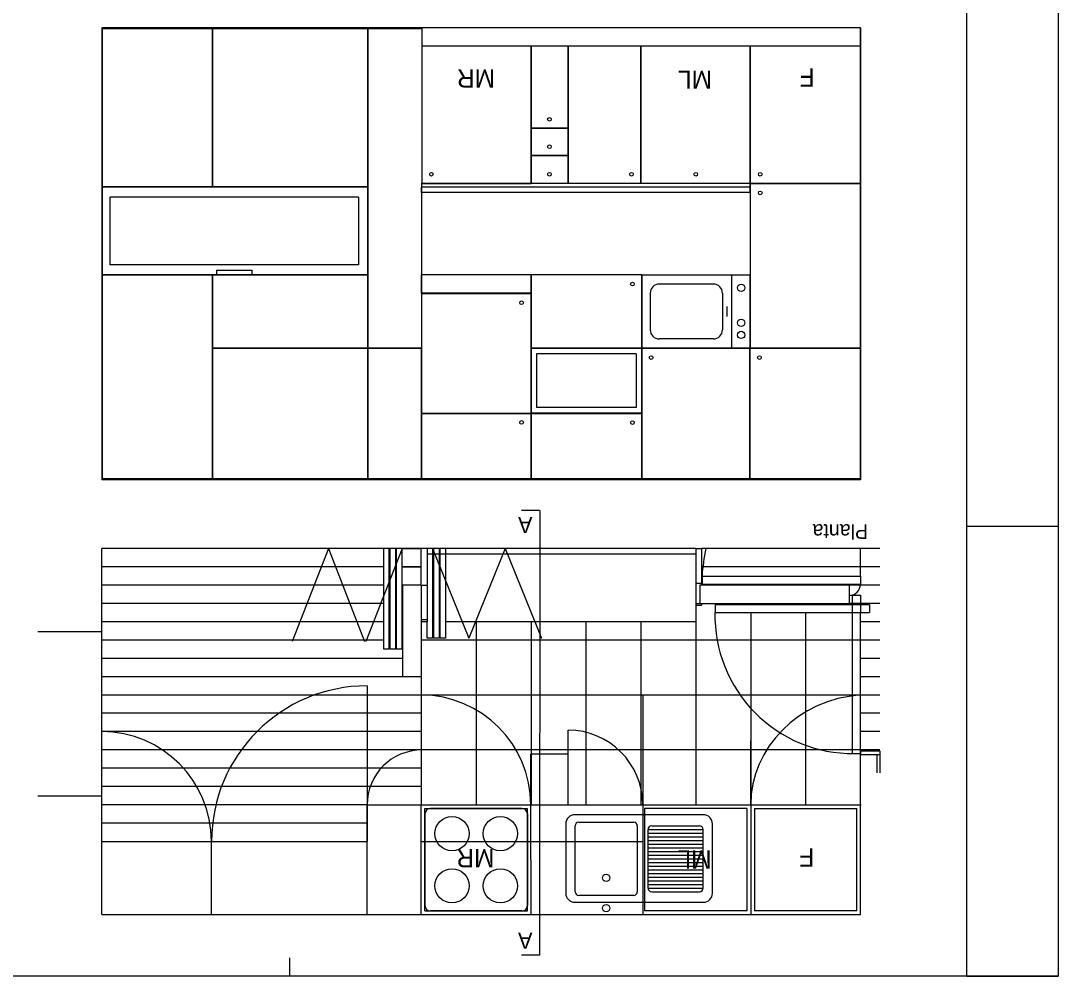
# Model space of a CAD drawing. Extents: x 1306.3 to 1323.2, y -308.3 to -299.9.
# Drawn here: x 1317.51 to 1323.18, y -308.35 to -303.12 of the extents above; entities that cross this region are included whole.
import ezdxf

# ---------------------------------------------------------------- set-up
doc = ezdxf.new("R2010")
doc.units = 0
for name, color, linetype in [('Level 1', 7, 'Continuous'), ('Level 10', 7, 'Continuous'), ('Level 11', 7, 'Continuous'), ('Level 13', 7, 'Continuous'), ('Level 2', 7, 'Continuous'), ('Level 3', 7, 'Continuous'), ('Level 31', 7, 'Continuous'), ('Level 37', 7, 'Continuous'), ('Level 4', 7, 'Continuous'), ('Level 59', 7, 'Continuous'), ('Level 60', 7, 'Continuous'), ('Level 62', 7, 'Continuous')]:
    doc.layers.add(name, color=color, linetype=linetype)

msp = doc.modelspace()

# ---------------------------------------------------------------- linework, layer by layer
at = {"layer": 'Level 1'}
for p, q in [((1322.0966, -303.1632), (1317.9505, -303.1632)), ((1317.9505, -303.1632), (1317.9505, -305.6332)), ((1322.0966, -303.1632), (1322.0966, -305.6332)), ((1322.0966, -305.6332), (1317.9505, -305.6332)), ((1317.9505, -306.4612), (1317.9505, -306.0087)), ((1319.6966, -306.2087), (1319.6966, -306.0087)), ((1319.7286, -306.0087), (1319.698, -306.0087)), ((1319.7286, -306.0087), (1319.7286, -306.4087)), ((1321.1966, -306.0087), (1321.1966, -306.3187)), ((1321.1966, -306.0087), (1321.2286, -306.0087)), ((1321.2286, -306.0087), (1321.2286, -306.2087)), ((1321.2286, -306.1987), (1321.1966, -306.1987)), ((1319.5966, -306.7087), (1319.5966, -306.2087)), ((1319.6966, -306.2087), (1319.5966, -306.2087)), ((1319.6966, -306.2087), (1319.6966, -306.7087)), ((1319.6966, -306.2087), (1319.7286, -306.2087)), ((1321.1966, -306.2087), (1321.1966, -306.3087)), ((1322.0366, -306.2087), (1321.2186, -306.2087)), ((1321.2186, -306.2087), (1321.2186, -306.3087)), ((1322.0366, -306.3087), (1322.0366, -306.2087)), ((1322.0366, -306.3087), (1322.0366, -306.2087)), ((1321.1966, -306.3087), (1322.0366, -306.3087)), ((1321.1966, -306.3087), (1322.0366, -306.3087)), ((1321.2186, -306.3087), (1322.0366, -306.3087)), ((1321.2286, -306.3087), (1321.2286, -306.3187)), ((1321.1966, -306.3187), (1321.2286, -306.3187)), ((1319.7286, -306.3987), (1319.6966, -306.3987)), ((1319.7286, -306.4087), (1319.6966, -306.4087)), ((1317.6005, -306.4612), (1317.9505, -306.4612)), ((1319.6966, -306.7087), (1319.5966, -306.7087)), ((1322.0966, -307.1337), (1322.2016, -307.1337)), ((1322.0966, -308.0087), (1322.0966, -307.1337)), ((1322.0966, -308.0087), (1322.0966, -307.1337)), ((1322.1866, -307.1337), (1322.1866, -307.2337)), ((1322.2016, -307.1337), (1322.2016, -307.2337)), ((1317.9505, -307.3612), (1317.6005, -307.3612)), ((1317.9505, -308.0087), (1317.9505, -307.3587)), ((1317.9505, -308.0087), (1317.9505, -307.3612)), ((1317.9505, -308.0087), (1322.0966, -308.0087)), ((1319.3966, -308.0087), (1322.0966, -308.0087))]:
    msp.add_line(p, q, dxfattribs=at)
at = {"layer": 'Level 10'}
for p, q in [((1319.6966, -306.0087), (1317.9505, -306.0087)), ((1319.5916, -306.0087), (1319.698, -306.0087)), ((1322.2016, -306.0087), (1321.2286, -306.0087)), ((1319.4916, -306.1087), (1317.9505, -306.1087)), ((1319.5916, -306.1087), (1319.698, -306.1087)), ((1319.6966, -306.1087), (1319.5916, -306.1087)), ((1322.2016, -306.1087), (1321.2286, -306.1087)), ((1319.4916, -306.2087), (1317.9505, -306.2087)), ((1319.5966, -306.2087), (1319.5916, -306.2087)), ((1322.2016, -306.2087), (1322.0366, -306.2087)), ((1319.4916, -306.3087), (1317.9505, -306.3087)), ((1319.5966, -306.3087), (1319.5916, -306.3087)), ((1322.2016, -306.3087), (1322.0366, -306.3087)), ((1321.1966, -306.3587), (1321.1966, -307.4087)), ((1321.4966, -306.3587), (1321.4966, -307.4087)), ((1321.7966, -306.3587), (1321.7966, -307.4087)), ((1322.0966, -307.1137), (1322.0966, -306.3587)), ((1319.4916, -306.4087), (1317.9505, -306.4087)), ((1319.5966, -306.4087), (1319.5916, -306.4087)), ((1319.9966, -306.4087), (1319.9966, -307.4087)), ((1320.2966, -306.4087), (1320.2966, -307.4087)), ((1320.5966, -306.4087), (1320.5966, -307.4087)), ((1320.8966, -306.4087), (1320.8966, -307.4087)), ((1322.2016, -306.4087), (1322.0966, -306.4087)), ((1319.4916, -306.5087), (1317.9505, -306.5087)), ((1319.5966, -306.5087), (1319.5916, -306.5087)), ((1322.0966, -306.5087), (1319.6966, -306.5087)), ((1322.2016, -306.5087), (1322.0966, -306.5087)), ((1319.5966, -306.6087), (1317.9505, -306.6087)), ((1322.2016, -306.6087), (1322.0966, -306.6087)), ((1319.5966, -306.7087), (1317.9505, -306.7087)), ((1319.6966, -306.7087), (1319.6966, -307.4057)), ((1322.2016, -306.7087), (1322.0966, -306.7087)), ((1322.0966, -306.8087), (1317.9505, -306.8087)), ((1322.2016, -306.8087), (1322.0966, -306.8087)), ((1319.6966, -306.9087), (1317.9505, -306.9087)), ((1322.2016, -306.9087), (1322.0966, -306.9087)), ((1319.6966, -307.0087), (1317.9505, -307.0087)), ((1322.2016, -307.0087), (1322.0966, -307.0087)), ((1322.0966, -307.1087), (1317.9505, -307.1087)), ((1322.2016, -307.1087), (1322.0966, -307.1087)), ((1319.6966, -307.2087), (1317.9505, -307.2087)), ((1319.6966, -307.3087), (1317.9505, -307.3087)), ((1319.4005, -307.4087), (1317.9505, -307.4087)), ((1319.4005, -307.5087), (1317.9505, -307.5087))]:
    msp.add_line(p, q, dxfattribs=at)
at = {"layer": 'Level 11'}
for p, q in [((1320.2946, -304.5132), (1319.6986, -304.5132)), ((1319.6986, -304.6132), (1319.6986, -304.5132)), ((1320.2946, -304.5132), (1320.2946, -304.6132)), ((1320.9026, -304.5132), (1320.9026, -304.9132)), ((1320.9026, -304.5132), (1321.4926, -304.5132)), ((1321.3926, -304.5132), (1321.3926, -304.9132)), ((1321.4926, -304.5132), (1321.4926, -304.9132)), ((1321.2926, -304.5632), (1320.9976, -304.5632)), ((1320.2946, -304.6132), (1319.6986, -304.6132)), ((1320.9476, -304.6132), (1320.9476, -304.8132)), ((1321.3426, -304.6132), (1321.3426, -304.8132)), ((1321.3671, -304.6864), (1321.3671, -304.7399)), ((1321.2926, -304.8632), (1320.9976, -304.8632)), ((1321.4926, -304.9132), (1320.9026, -304.9132)), ((1320.2466, -307.4286), (1319.7466, -307.4286)), ((1321.5166, -307.4287), (1322.0766, -307.4287)), ((1321.5166, -307.4287), (1321.5166, -307.9887)), ((1322.0766, -307.9887), (1322.0766, -307.4287)), ((1319.7166, -307.4586), (1319.7166, -307.9586)), ((1320.2766, -307.4586), (1320.2766, -307.9586)), ((1320.557, -307.5036), (1320.857, -307.5036)), ((1320.537, -307.8836), (1320.537, -307.5236)), ((1320.877, -307.5236), (1320.877, -307.8836)), ((1320.9355, -307.8636), (1320.9355, -307.5436)), ((1320.9355, -307.5436), (1321.237, -307.5436)), ((1320.9555, -307.5236), (1321.217, -307.5236)), ((1321.237, -307.8636), (1321.237, -307.5436)), ((1320.9355, -307.5636), (1321.237, -307.5636)), ((1320.9355, -307.5836), (1321.237, -307.5836)), ((1320.9355, -307.6036), (1321.237, -307.6036)), ((1320.9355, -307.6236), (1321.237, -307.6236)), ((1320.9355, -307.6436), (1321.237, -307.6436)), ((1320.9355, -307.6636), (1321.237, -307.6636)), ((1320.9355, -307.6836), (1321.237, -307.6836)), ((1320.9355, -307.7036), (1321.237, -307.7036)), ((1320.9355, -307.7236), (1321.237, -307.7236)), ((1320.9355, -307.7436), (1321.237, -307.7436)), ((1320.9355, -307.7636), (1321.237, -307.7636)), ((1320.9355, -307.7836), (1321.237, -307.7836)), ((1320.9355, -307.8036), (1321.237, -307.8036)), ((1320.9355, -307.8236), (1321.237, -307.8236)), ((1320.9355, -307.8436), (1321.237, -307.8436)), ((1320.9355, -307.8636), (1321.237, -307.8636)), ((1320.9555, -307.8836), (1321.217, -307.8836)), ((1320.857, -307.9036), (1320.557, -307.9036)), ((1320.2466, -307.9886), (1319.7466, -307.9886)), ((1322.0766, -307.9887), (1321.5166, -307.9887))]:
    msp.add_line(p, q, dxfattribs=at)
for points in [[(1321.2373, -307.463), (1320.5359, -307.463)], [(1320.4859, -307.513), (1320.4859, -307.8914)], [(1321.2873, -307.8914), (1321.2873, -307.513)], [(1320.5359, -307.9414), (1321.2373, -307.9414)]]:
    msp.add_lwpolyline(points, dxfattribs=at)
for centre, radius in [((1321.4444, -304.5842), 0.02), ((1321.4444, -304.7749), 0.02), ((1321.4444, -304.8413), 0.02), ((1319.8645, -307.566), 0.0936), ((1320.1287, -307.566), 0.0936), ((1319.8645, -307.8512), 0.0936), ((1320.1287, -307.8512), 0.0936), ((1320.707, -307.8076), 0.0199), ((1320.707, -307.9736), 0.0199)]:
    msp.add_circle(centre, radius, dxfattribs=at)
for centre, radius, start, end in [((1320.9976, -304.6132), 0.05, 90, 180), ((1321.2926, -304.6132), 0.05, 0, 90), ((1320.9976, -304.8132), 0.05, 180, 270), ((1321.2926, -304.8132), 0.05, 270, 0), ((1319.7466, -307.4586), 0.03, 90, 179.9999), ((1320.2466, -307.4586), 0.03, 359.9999, 89.9999), ((1320.5359, -307.513), 0.05, 90, 180), ((1320.557, -307.5236), 0.02, 90, 180), ((1320.857, -307.5236), 0.02, 0, 90), ((1321.2373, -307.513), 0.05, 0, 90), ((1320.9555, -307.5436), 0.02, 90, 180), ((1321.217, -307.5436), 0.02, 0, 90), ((1320.5359, -307.8914), 0.05, 180, 270), ((1320.557, -307.8836), 0.02, 180, 270), ((1320.857, -307.8836), 0.02, 270, 0), ((1320.9555, -307.8636), 0.02, 180, 270), ((1321.217, -307.8636), 0.02, 270, 0), ((1321.2373, -307.8914), 0.05, 270, 0), ((1319.7466, -307.9586), 0.03, 180, 269.9998), ((1320.2466, -307.9586), 0.03, 269.9998, 0.0001)]:
    msp.add_arc(centre, radius, start, end, dxfattribs=at)
at = {"layer": 'Level 13'}
for p, q in [((1318.4225, -303.1682), (1317.9505, -303.1682)), ((1317.9525, -303.1682), (1317.9525, -304.0312)), ((1317.9525, -303.1682), (1317.9525, -304.5132)), ((1319.6966, -303.1682), (1318.4245, -303.1682)), ((1318.5545, -303.1682), (1318.5545, -304.0312)), ((1318.5565, -303.1682), (1318.5565, -304.0312)), ((1319.4025, -303.1632), (1319.4025, -304.0312)), ((1319.4045, -303.1632), (1319.4045, -304.9132)), ((1319.6993, -303.1632), (1319.6993, -304.0132)), ((1322.0946, -303.1632), (1322.0946, -304.9127)), ((1321.4986, -303.2632), (1319.6993, -303.2632)), ((1320.2943, -303.2632), (1319.6993, -303.2632)), ((1319.6993, -303.2632), (1319.6993, -304.0112)), ((1320.2946, -303.2632), (1320.2946, -304.0132)), ((1320.2966, -303.2632), (1320.2966, -303.7112)), ((1320.4966, -303.2632), (1320.4966, -303.7112)), ((1320.4986, -303.2632), (1320.4986, -304.0132)), ((1320.8946, -303.2632), (1320.8946, -304.0132)), ((1320.8966, -303.2632), (1320.8966, -304.0132)), ((1321.4926, -303.2632), (1321.4926, -304.0332)), ((1321.4946, -303.2632), (1321.4946, -304.9127)), ((1322.0946, -303.2632), (1321.4986, -303.2632)), ((1322.0946, -303.2632), (1322.0946, -305.6282)), ((1320.4966, -303.7112), (1320.2966, -303.7112)), ((1320.4966, -303.7132), (1320.2966, -303.7132)), ((1320.2966, -303.7132), (1320.2966, -303.8612)), ((1320.4966, -303.7132), (1320.4966, -303.8612)), ((1320.4966, -303.8612), (1320.2966, -303.8612)), ((1320.4966, -303.8632), (1320.2966, -303.8632)), ((1320.2966, -303.8632), (1320.2966, -304.0132)), ((1320.4966, -303.8632), (1320.4966, -304.0132)), ((1318.5545, -304.0312), (1317.9525, -304.0312)), ((1319.4025, -304.0332), (1317.9525, -304.0332)), ((1319.4025, -304.0312), (1318.5565, -304.0312)), ((1319.4025, -304.0332), (1319.4025, -304.5132)), ((1320.2946, -304.0132), (1319.6966, -304.0132)), ((1319.6986, -304.0132), (1319.6986, -305.6282)), ((1319.6993, -304.0132), (1320.2968, -304.0132)), ((1320.4966, -304.0132), (1320.2966, -304.0132)), ((1321.4926, -304.0132), (1320.4966, -304.0132)), ((1322.0946, -304.0132), (1321.4946, -304.0132)), ((1322.0946, -304.0152), (1321.4946, -304.0152)), ((1319.3543, -304.0882), (1317.9955, -304.0882)), ((1317.9955, -304.0882), (1317.9955, -304.4582)), ((1319.3543, -304.0882), (1319.3543, -304.4582)), ((1319.3543, -304.4582), (1317.9955, -304.4582)), ((1318.5774, -304.4882), (1318.7724, -304.4882)), ((1318.5774, -304.4882), (1318.5774, -304.5132)), ((1318.7724, -304.5132), (1318.7724, -304.4882)), ((1319.4025, -304.5132), (1317.9525, -304.5132)), ((1317.9525, -304.5152), (1317.9525, -305.6282)), ((1318.5545, -304.5152), (1317.9525, -304.5152)), ((1318.5545, -304.5152), (1318.5545, -305.6282)), ((1318.5565, -304.5132), (1318.7515, -304.5132)), ((1319.4025, -304.5152), (1318.5565, -304.5152)), ((1318.5565, -304.5152), (1318.5565, -304.9132)), ((1319.4025, -304.5152), (1319.4025, -304.9132)), ((1320.9026, -304.5132), (1320.2946, -304.5132)), ((1320.2966, -304.5132), (1320.2966, -304.9132)), ((1320.9006, -304.5132), (1320.9006, -304.9132)), ((1319.6986, -304.6152), (1320.2946, -304.6152)), ((1320.2946, -304.6152), (1320.2946, -305.2682)), ((1319.4025, -304.9132), (1318.5565, -304.9132)), ((1318.5565, -304.9152), (1318.5565, -305.6282)), ((1319.0485, -304.9152), (1318.5565, -304.9152)), ((1319.4025, -304.9152), (1319.0505, -304.9152)), ((1319.4025, -304.9152), (1319.4025, -305.6282)), ((1319.6986, -304.9132), (1319.4045, -304.9132)), ((1319.4045, -304.9152), (1319.4045, -305.6282)), ((1319.6966, -304.9152), (1319.4045, -304.9152)), ((1319.6966, -304.9132), (1319.6966, -305.6282)), ((1320.9006, -304.9132), (1320.2966, -304.9132)), ((1320.2966, -304.9152), (1320.2966, -305.2682)), ((1320.9006, -304.9152), (1320.2966, -304.9152)), ((1320.8706, -304.9447), (1320.3266, -304.9447)), ((1320.3266, -304.9447), (1320.3266, -305.2382)), ((1320.8706, -304.9447), (1320.8706, -305.2382)), ((1320.9006, -304.9152), (1320.9006, -305.2682)), ((1320.9026, -304.9152), (1320.9026, -305.6282)), ((1321.4926, -304.9152), (1320.9026, -304.9152)), ((1321.4926, -305.6282), (1321.4926, -304.9152)), ((1322.0946, -304.9127), (1321.4946, -304.9127)), ((1321.4946, -305.6282), (1321.4946, -304.9152)), ((1322.0946, -304.9152), (1321.4946, -304.9152)), ((1322.0946, -304.9152), (1322.0946, -305.6282)), ((1319.6986, -305.2682), (1320.2946, -305.2682)), ((1319.6986, -305.2702), (1320.2946, -305.2702)), ((1320.2946, -305.2702), (1320.2946, -305.6282)), ((1320.9006, -305.2682), (1320.2966, -305.2682)), ((1320.2966, -305.2702), (1320.2966, -305.6282)), ((1320.2966, -305.2702), (1320.9006, -305.2702)), ((1320.8706, -305.2382), (1320.3266, -305.2382)), ((1320.9006, -305.2702), (1320.9006, -305.6282)), ((1318.5545, -305.6282), (1317.9525, -305.6282)), ((1319.4025, -305.6282), (1318.5565, -305.6282)), ((1319.6966, -305.6282), (1319.4045, -305.6282)), ((1320.2946, -305.6282), (1319.6986, -305.6282)), ((1320.9006, -305.6282), (1320.2966, -305.6282)), ((1321.6471, -305.6282), (1320.9026, -305.6282)), ((1322.0946, -305.6282), (1321.6491, -305.6282)), ((1319.4916, -306.5587), (1319.4916, -306.0087)), ((1319.5916, -306.0087), (1319.4916, -306.0087)), ((1319.5916, -306.0087), (1319.4916, -306.0087)), ((1319.5216, -306.5587), (1319.5216, -306.0087)), ((1319.5266, -306.5587), (1319.5266, -306.0087)), ((1319.5566, -306.5587), (1319.5566, -306.0087)), ((1319.5616, -306.5587), (1319.5616, -306.0087)), ((1319.5916, -306.5587), (1319.5916, -306.0087)), ((1321.1966, -306.0087), (1319.7286, -306.0087)), ((1319.7586, -306.0087), (1319.7586, -306.4987)), ((1319.7636, -306.0087), (1319.7636, -306.4987)), ((1319.7936, -306.0087), (1319.7936, -306.4987)), ((1319.7986, -306.0087), (1319.7986, -306.4987)), ((1319.8286, -306.0087), (1319.8286, -306.4987)), ((1321.2308, -306.1587), (1322.0966, -306.1587)), ((1321.2308, -306.1587), (1321.2308, -306.2037)), ((1322.0966, -306.1587), (1322.0966, -306.2037)), ((1321.2308, -306.2037), (1322.0966, -306.2037)), ((1321.3016, -306.3137), (1322.1466, -306.3137)), ((1321.3016, -306.3137), (1321.3016, -306.3587)), ((1321.3016, -306.3587), (1322.1466, -306.3587)), ((1322.1466, -306.3137), (1322.1466, -306.3587)), ((1319.7286, -306.4987), (1319.7286, -306.4087)), ((1319.7586, -306.4987), (1319.7286, -306.4987)), ((1319.7936, -306.4987), (1319.7636, -306.4987)), ((1319.8286, -306.4987), (1319.7986, -306.4987)), ((1319.5216, -306.5587), (1319.4916, -306.5587)), ((1319.5566, -306.5587), (1319.5266, -306.5587)), ((1319.5916, -306.5587), (1319.5616, -306.5587)), ((1319.4005, -308.0087), (1319.4005, -307.4087)), ((1319.4005, -307.4087), (1322.1005, -307.4087)), ((1321.4966, -307.4087), (1321.4966, -308.0087)), ((1317.9505, -307.6087), (1319.4005, -307.6087))]:
    msp.add_line(p, q, dxfattribs=at)
for centre in [(1320.3966, -303.6632), (1320.3966, -303.8132), (1319.7517, -303.9632), (1319.7517, -303.9632), (1320.3966, -303.9632), (1320.8446, -303.9632), (1321.1966, -303.9632), (1321.5486, -303.9632), (1321.5486, -304.0652), (1320.8506, -304.5632), (1320.2446, -304.6652), (1320.9526, -304.9647), (1321.5446, -304.9647), (1320.2446, -305.3197), (1320.8506, -305.3202)]:
    msp.add_circle(centre, 0.01, dxfattribs=at)
at = {"layer": 'Level 2'}
for p, q in [((1321.1966, -306.3187), (1321.1966, -306.4087)), ((1319.7636, -306.4087), (1319.7586, -306.4087)), ((1319.7636, -306.4087), (1319.7586, -306.4087)), ((1319.7986, -306.4087), (1319.7936, -306.4087)), ((1319.7986, -306.4087), (1319.7936, -306.4087)), ((1321.1966, -306.4087), (1319.8286, -306.4087)), ((1317.9505, -307.3612), (1317.9505, -306.4612)), ((1317.9505, -307.3612), (1317.9505, -306.4612))]:
    msp.add_line(p, q, dxfattribs=at)
at = {"layer": 'Level 3'}
for p, q in [((1319.6966, -307.6087), (1319.6966, -307.4087)), ((1320.9066, -307.4087), (1320.9066, -308.0087)), ((1318.5505, -308.0087), (1318.5505, -307.6087)), ((1319.6966, -307.6087), (1320.9066, -307.6087))]:
    msp.add_line(p, q, dxfattribs=at)
at = {"layer": 'Level 31'}
for p, q in [((1322.0966, -307.1137), (1322.2016, -307.1137)), ((1322.0966, -307.1137), (1322.0966, -307.1337)), ((1322.2016, -307.1137), (1322.2016, -307.1337))]:
    msp.add_line(p, q, dxfattribs=at)
at = {"layer": 'Level 37'}
for p, q in [((1321.4926, -304.0332), (1319.6986, -304.0332)), ((1319.6986, -304.0632), (1319.6986, -304.0332)), ((1321.4926, -304.0332), (1321.4926, -304.0632)), ((1321.4926, -304.0632), (1319.6986, -304.0632))]:
    msp.add_line(p, q, dxfattribs=at)
at = {"layer": 'Level 4'}
for p, q in [((1319.1891, -306.0087), (1318.9919, -306.516)), ((1319.1891, -306.0087), (1319.3863, -306.516)), ((1319.5916, -306.0087), (1319.3944, -306.516)), ((1319.7586, -306.0087), (1319.9568, -306.4987)), ((1320.1551, -306.0087), (1319.9568, -306.4987)), ((1320.1551, -306.0087), (1320.3533, -306.4987)), ((1322.0966, -306.1587), (1322.0966, -306.0087)), ((1321.1966, -306.0387), (1319.7286, -306.0387)), ((1319.7636, -306.0387), (1319.7586, -306.0387)), ((1319.7986, -306.0387), (1319.7936, -306.0387)), ((1322.0516, -306.2637), (1322.0516, -307.1287)), ((1322.0516, -306.2637), (1322.0966, -306.2637)), ((1322.0966, -306.2637), (1322.0966, -306.3587)), ((1319.4005, -306.7587), (1319.4005, -307.6087)), ((1320.9066, -306.8087), (1320.9066, -307.4087)), ((1321.4966, -306.8087), (1320.9066, -306.8087)), ((1322.0966, -307.4087), (1322.0966, -306.8087)), ((1320.4986, -307.4087), (1320.4986, -307.0007)), ((1321.4966, -307.4087), (1321.4966, -307.0587)), ((1320.4986, -307.1313), (1320.2943, -307.1313)), ((1320.2943, -307.4087), (1320.2943, -307.1313)), ((1322.0616, -307.1287), (1322.0966, -307.1287)), ((1319.7166, -307.4287), (1320.2766, -307.4287)), ((1319.7166, -307.9887), (1319.7166, -307.4287)), ((1320.2766, -307.9887), (1320.2766, -307.4287)), ((1320.2966, -308.0087), (1320.2943, -307.4087)), ((1321.4766, -307.4287), (1320.9166, -307.4287)), ((1320.9166, -307.4287), (1320.9166, -307.9887)), ((1321.4766, -307.9887), (1321.4766, -307.4287)), ((1322.0966, -308.0087), (1322.0966, -307.4087)), ((1319.6966, -308.0087), (1319.6966, -307.6087)), ((1319.7166, -307.9887), (1320.2766, -307.9887)), ((1321.4766, -307.9887), (1320.9166, -307.9887))]:
    msp.add_line(p, q, dxfattribs=at)
for centre, radius, start, end in [((1322.0366, -306.2037), 0.06, 269.997, 0.0014), ((1322.0554, -306.3745), 0.7542, 178.8015, 270.4703), ((1319.6943, -307.4087), 0.6, 0, 89.7775), ((1317.9505, -307.6087), 0.6, 0, 90), ((1320.4986, -307.4087), 0.408, 0, 90), ((1319.7005, -307.4087), 0.3, 90, 180)]:
    msp.add_arc(centre, radius, start, end, dxfattribs=at)
for centre, major_axis, ratio, start_param, end_param in [((1322.0286, -306.2267), (0, -0.9179), 0.871521, 4.472668, 4.638298), ((1319.4005, -307.6087), (0, -0.85), 0.999998, 3.141593, 4.712389), ((1322.1475, -307.4087), (-0.6509, 0), 0.924693, 4.790593, 6.283185)]:
    msp.add_ellipse(centre, major_axis=major_axis, ratio=ratio, start_param=start_param, end_param=end_param, dxfattribs=at)
at = {"layer": 'Level 59'}
for p, q in [((1320.3431, -305.8013), (1320.2433, -305.8013)), ((1320.3447, -305.8013), (1320.3431, -308.2302)), ((1320.3431, -308.2302), (1320.2433, -308.2302))]:
    msp.add_line(p, q, dxfattribs=at)
at = {"layer": 'Level 62'}
for p, q in [((1322.6772, -308.3454), (1322.6772, -299.9454)), ((1322.6772, -305.8854), (1323.1772, -305.8854)), ((1318.9768, -308.2454), (1318.9768, -308.3454)), ((1322.6772, -308.3454), (1323.1772, -308.3454))]:
    msp.add_line(p, q, dxfattribs=at)
msp.add_lwpolyline([(1323.1772, -299.9454), (1323.1772, -308.3454), (1311.5776, -308.3454), (1311.5776, -299.9454)], close=True, dxfattribs=at)

# ---------------------------------------------------------------- texts
at = {"layer": 'Level 11'}
for s, p in [('MR', (1320.0993, -303.3899)), ('ML', (1321.2852, -303.3965)), ('F', (1321.8462, -303.3849)), ('MR', (1320.0967, -307.651)), ('ML', (1321.2826, -307.6576)), ('F', (1321.8435, -307.6459))]:
    msp.add_text(s, height=0.1, rotation=180, dxfattribs=at).set_placement(p)
at = {"layer": 'Level 59'}
for rotation, p in [(180.0002, (1320.304, -305.8359)), (179.9998, (1320.304, -308.1076))]:
    msp.add_text('A', height=0.088, rotation=rotation, dxfattribs=at).set_placement(p)
at = {"layer": 'Level 60'}
msp.add_text('Planta', height=0.08, rotation=180, dxfattribs=at).set_placement((1322.1378, -305.8754))

doc.saveas('drawing.dxf')
